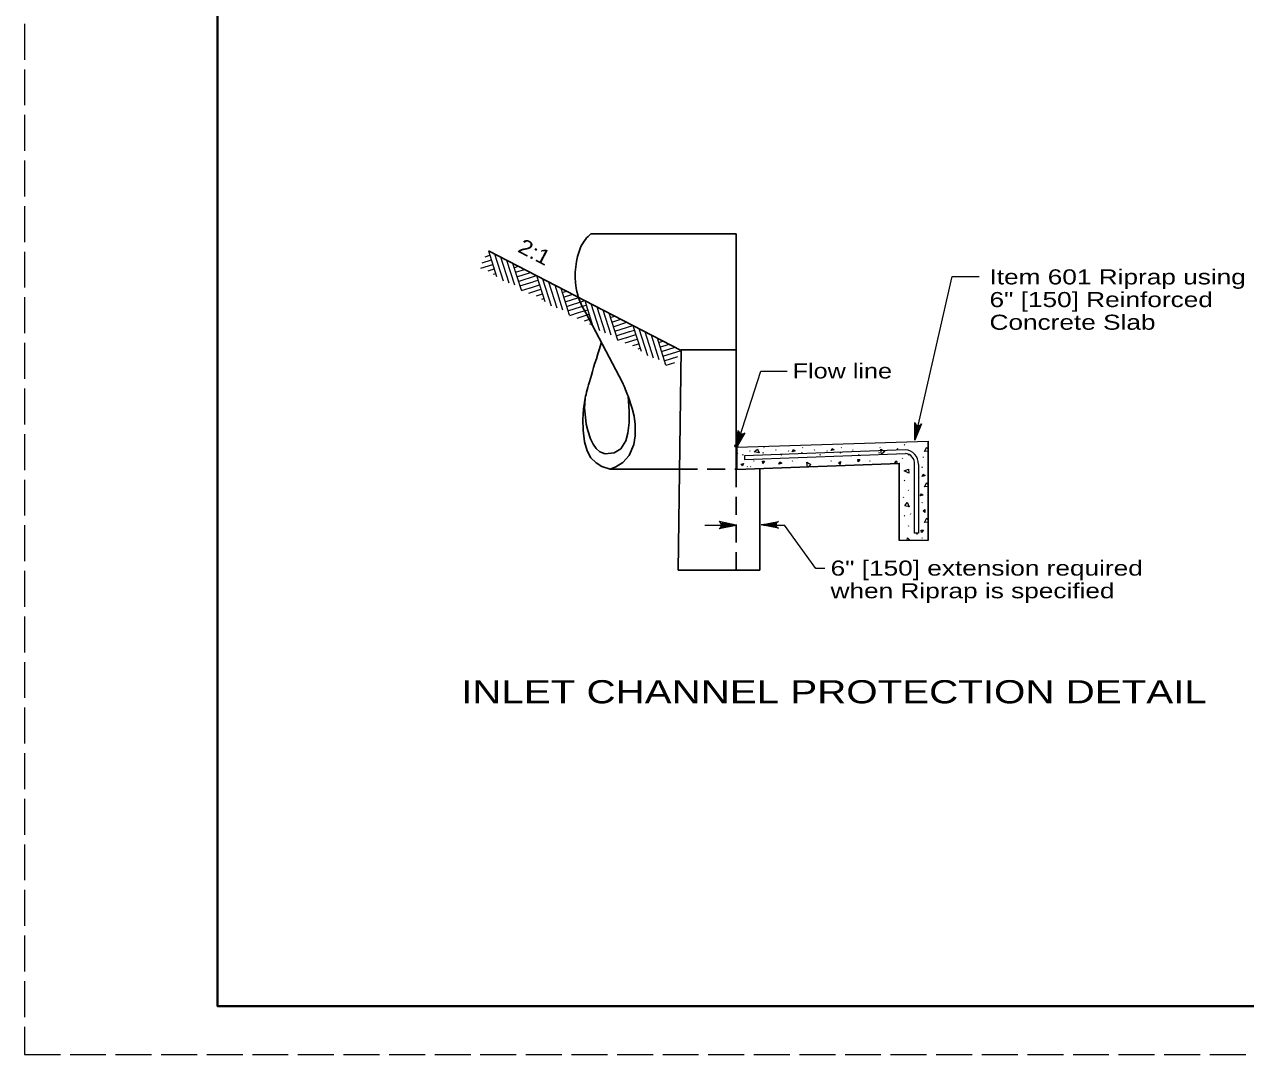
# Model space of a CAD drawing. Extents: x 685.4 to 719.4, y 1059.8 to 1105.8.
# Drawn here: x 685.44 to 698.08, y 1083.77 to 1094.44 of the extents above; entities that cross this region are included whole.
import ezdxf
from ezdxf.enums import TextEntityAlignment as Align

# ---------------------------------------------------------------- set-up
doc = ezdxf.new("R2010")
doc.units = 0
doc.header["$LTSCALE"] = 0.062
doc.header["$PDMODE"] = 32
doc.header["$PDSIZE"] = 0.031
doc.linetypes.add('LONG_DASHED', pattern=[7.5, 6, -1.5])
doc.linetypes.add('MEDIUM_DASHED', pattern=[4.5, 3, -1.5])
doc.layers.add('1', color=7, linetype='Continuous', lineweight=13)

msp = doc.modelspace()

# ---------------------------------------------------------------- linework, layer by layer
at = {"layer": '1', "lineweight": 25}
for p, q in [((691.30642, 1092.26917), (692.80992, 1092.26892)), ((692.31017, 1092.26892), (692.80992, 1092.26892)), ((690.24483, 1092.09333), (692.23983, 1091.06167)), ((691.63242, 1090.72958), (691.25267, 1091.451)), ((692.21025, 1088.78575), (692.24117, 1091.066)), ((692.24117, 1091.066), (692.80992, 1091.066)), ((692.80992, 1089.83158), (692.80992, 1090.05208)), ((694.79625, 1090.12158), (694.79625, 1089.09375)), ((691.50508, 1089.83183), (692.22567, 1089.83175)), ((693.0545, 1088.78575), (693.0545, 1089.83158)), ((692.21025, 1088.78575), (693.0545, 1088.78575))]:
    msp.add_line(p, q, dxfattribs=at)
at = {"layer": '1'}
for p, q in [((690.24483, 1092.09333), (690.32992, 1091.82583)), ((690.30708, 1092.06108), (690.39608, 1091.78167)), ((690.16467, 1091.91158), (690.29, 1091.95142)), ((690.18025, 1091.96858), (690.275, 1091.99867)), ((690.21258, 1092.031), (690.25992, 1092.04608)), ((690.36942, 1092.02883), (690.45542, 1091.75892)), ((690.43192, 1091.9965), (690.51367, 1091.73942)), ((690.49417, 1091.96442), (690.58267, 1091.6865)), ((690.24275, 1091.88433), (690.305, 1091.90417)), ((690.29783, 1091.84983), (690.32, 1091.85683)), ((690.50917, 1091.91708), (690.5565, 1091.93217)), ((690.52425, 1091.86967), (690.619, 1091.89983)), ((690.53933, 1091.8225), (690.68125, 1091.86758)), ((690.55442, 1091.77525), (690.74358, 1091.83533)), ((690.74358, 1091.83533), (690.82867, 1091.56783)), ((690.56942, 1091.72792), (690.70942, 1091.7725)), ((690.58842, 1091.68183), (690.67708, 1091.71)), ((690.66342, 1091.65367), (690.78875, 1091.6935)), ((690.679, 1091.71058), (690.77367, 1091.74075)), ((690.71133, 1091.77308), (690.75858, 1091.78817)), ((690.80592, 1091.80317), (690.89483, 1091.52375)), ((690.86817, 1091.771), (690.95408, 1091.501)), ((690.93067, 1091.73867), (691.01242, 1091.4815)), ((690.993, 1091.70642), (691.08133, 1091.4285)), ((690.74142, 1091.62642), (690.80375, 1091.64625)), ((690.79667, 1091.59192), (690.81883, 1091.599)), ((691.00792, 1091.65917), (691.05525, 1091.67425)), ((691.023, 1091.61183), (691.11767, 1091.64192)), ((691.03808, 1091.5645), (691.17992, 1091.60967)), ((691.05308, 1091.51733), (691.24225, 1091.5775)), ((691.24225, 1091.5775), (691.3275, 1091.31)), ((691.06817, 1091.47), (691.20817, 1091.51458)), ((691.08717, 1091.42383), (691.17592, 1091.45208)), ((691.16217, 1091.39567), (691.2875, 1091.43558)), ((691.17783, 1091.45275), (691.27242, 1091.48283)), ((691.21008, 1091.51517), (691.25733, 1091.53025)), ((691.30467, 1091.54525), (691.3935, 1091.26575)), ((691.36692, 1091.51308), (691.45283, 1091.24308)), ((691.42933, 1091.48075), (691.51125, 1091.22358)), ((691.49167, 1091.4485), (691.58008, 1091.17067)), ((691.24017, 1091.3685), (691.3025, 1091.38833)), ((691.29542, 1091.334), (691.31758, 1091.34108)), ((691.50675, 1091.40125), (691.55392, 1091.41625)), ((691.52183, 1091.35392), (691.61642, 1091.384)), ((691.53683, 1091.30658), (691.67875, 1091.35183)), ((691.55183, 1091.25933), (691.741, 1091.31958)), ((691.741, 1091.31958), (691.82617, 1091.05208)), ((691.56692, 1091.21217), (691.707, 1091.25658)), ((691.58592, 1091.166), (691.67467, 1091.19425)), ((691.66092, 1091.13775), (691.78617, 1091.17767)), ((691.67658, 1091.19483), (691.77117, 1091.225)), ((691.70883, 1091.25725), (691.75608, 1091.27225)), ((691.80333, 1091.28733), (691.89225, 1091.00792)), ((691.86567, 1091.25508), (691.95158, 1090.98517)), ((691.92808, 1091.22283), (692.01, 1090.96567)), ((691.99042, 1091.19058), (692.07883, 1090.91275)), ((691.73892, 1091.11058), (691.80125, 1091.13042)), ((691.79408, 1091.07608), (691.81633, 1091.08317)), ((692.0055, 1091.14333), (692.05275, 1091.15842)), ((692.02058, 1091.096), (692.11517, 1091.12608)), ((692.03558, 1091.04875), (692.1775, 1091.09392)), ((692.05067, 1091.00142), (692.23983, 1091.06167)), ((692.06567, 1090.95425), (692.20567, 1090.99875)), ((692.08458, 1090.90808), (692.17342, 1090.93633)), ((691.6925, 1090.57925), (691.69067, 1090.58125)), ((691.69908, 1090.55908), (691.69192, 1090.56775)), ((691.24142, 1090.45875), (691.23075, 1090.47133)), ((691.24125, 1090.46367), (691.23133, 1090.47542)), ((691.24425, 1090.52658), (691.2405, 1090.53108)), ((692.83858, 1090.21142), (692.80992, 1090.05208)), ((692.84742, 1090.20275), (692.80992, 1090.05208)), ((692.884, 1090.19842), (692.80992, 1090.05208)), ((692.85767, 1090.19758), (692.80992, 1090.05208)), ((692.87225, 1090.19575), (692.80992, 1090.05208)), ((694.715, 1090.28742), (694.65933, 1090.13308)), ((694.67808, 1090.28725), (694.65933, 1090.13308)), ((694.68892, 1090.28342), (694.65933, 1090.13308)), ((694.70358, 1090.28342), (694.65933, 1090.13308)), ((692.81658, 1090.05992), (694.79625, 1090.12158)), ((693.09658, 1090.05658), (693.10008, 1090.05125)), ((693.49642, 1090.05658), (693.49992, 1090.05125)), ((693.89625, 1090.05658), (693.89975, 1090.05125)), ((694.29608, 1090.05658), (694.29958, 1090.05125)), ((694.47875, 1090.03942), (694.48225, 1090.04742)), ((694.55058, 1090.07842), (694.55425, 1090.08642)), ((692.81658, 1090.03358), (692.81992, 1090.02875)), ((692.81658, 1089.98042), (692.81708, 1089.98058)), ((692.81658, 1089.98042), (692.81708, 1089.98058)), ((692.8245, 1089.99808), (692.82692, 1089.9945)), ((692.87958, 1089.97775), (692.88308, 1089.98558)), ((694.56025, 1090.03208), (692.89742, 1089.97025)), ((692.95142, 1090.01658), (692.95492, 1090.02458)), ((692.99042, 1089.92092), (692.99392, 1089.91558)), ((693.08992, 1089.99808), (693.09342, 1090.00608)), ((693.21608, 1090.03408), (693.21975, 1090.02875)), ((693.27925, 1089.97775), (693.28292, 1089.98558)), ((693.35125, 1090.01658), (693.35475, 1090.02458)), ((693.39025, 1089.92092), (693.39375, 1089.91558)), ((693.48975, 1089.99808), (693.49325, 1090.00608)), ((693.61592, 1090.03408), (693.61942, 1090.02875)), ((693.67908, 1089.97775), (693.68275, 1089.98558)), ((693.75108, 1090.01658), (693.75458, 1090.02458)), ((693.79008, 1089.92092), (693.79358, 1089.91558)), ((693.88958, 1089.99808), (693.89308, 1090.00608)), ((694.01575, 1090.03408), (694.01925, 1090.02875)), ((694.07892, 1089.97775), (694.08242, 1089.98558)), ((694.15092, 1090.01658), (694.15442, 1090.02458)), ((694.18992, 1089.92092), (694.19342, 1089.91558)), ((694.28925, 1089.99808), (694.29292, 1090.00608)), ((694.41558, 1090.03408), (694.41908, 1090.02875)), ((694.53258, 1089.94192), (694.53608, 1089.94992)), ((694.58975, 1089.98258), (694.59325, 1089.97725)), ((694.74575, 1089.95925), (694.74675, 1089.95125)), ((694.79625, 1090.01858), (694.75958, 1090.01542)), ((692.92475, 1089.85975), (692.92717, 1089.85617)), ((692.95883, 1089.85842), (692.96125, 1089.85483)), ((694.69725, 1089.88142), (694.69725, 1089.16908)), ((694.73475, 1089.85042), (694.73825, 1089.85842)), ((694.55058, 1089.71108), (694.55425, 1089.71908)), ((694.69592, 1089.75108), (694.69942, 1089.74575)), ((694.53942, 1089.54675), (694.54042, 1089.53875)), ((694.58975, 1089.61525), (694.59325, 1089.60992)), ((694.79625, 1089.65125), (694.75958, 1089.64825)), ((694.73475, 1089.48308), (694.73825, 1089.49108)), ((694.55058, 1089.34375), (694.55425, 1089.35175)), ((694.61558, 1089.36558), (694.61908, 1089.37358)), ((694.69592, 1089.38375), (694.69942, 1089.37842)), ((694.79625, 1089.28392), (694.75958, 1089.28092)), ((692.486, 1089.25267), (692.80992, 1089.25267)), ((692.64783, 1089.22792), (692.80992, 1089.25267)), ((692.64967, 1089.27508), (692.80992, 1089.25267)), ((692.65392, 1089.23833), (692.80992, 1089.25267)), ((692.65517, 1089.264), (692.80992, 1089.25267)), ((692.65675, 1089.25267), (692.80992, 1089.25267)), ((693.22958, 1089.27708), (693.06933, 1089.25475)), ((693.22417, 1089.26592), (693.06933, 1089.25475)), ((693.2225, 1089.25475), (693.06933, 1089.25475)), ((693.22533, 1089.24025), (693.06933, 1089.25475)), ((693.2315, 1089.22992), (693.06933, 1089.25475)), ((693.09333, 1089.25325), (693.30933, 1089.25325)), ((694.58975, 1089.24792), (694.59325, 1089.24275)), ((694.67942, 1089.16292), (694.68025, 1089.15492)), ((694.79625, 1089.09375), (694.49825, 1089.09375)), ((694.73475, 1089.11575), (694.73825, 1089.12375))]:
    msp.add_line(p, q, dxfattribs=at)
at = {"layer": '1', "linetype": 'MEDIUM_DASHED', "lineweight": 25}
for p in [(692.22442, 1089.83167), (692.80992, 1088.78575)]:
    msp.add_line(p, (692.80992, 1089.83158), dxfattribs=at)
at = {"layer": '1', "linetype": 'LONG_DASHED'}
msp.add_lwpolyline([(685.44108, 1083.77067), (719.44108, 1083.77067), (719.44108, 1105.77067), (685.44108, 1105.77067)], close=True, dxfattribs=at)
at = {"layer": '1', "lineweight": 25}
for points in [[(718.94108, 1084.27067), (687.44108, 1084.27067), (687.44108, 1105.27067)], [(692.80992, 1089.83158), (692.80992, 1090.07333), (692.80992, 1092.26892)], [(691.69033, 1090.58583), (691.7315, 1090.46125), (691.75208, 1090.38008), (691.76508, 1090.293), (691.76475, 1090.17633), (691.75142, 1090.08758), (691.70333, 1089.97208), (691.63775, 1089.90017), (691.56467, 1089.85483), (691.50508, 1089.83183), (691.41975, 1089.85808), (691.361, 1089.89658), (691.3065, 1089.94908), (691.26542, 1090.02283), (691.23808, 1090.11575), (691.22458, 1090.23633), (691.22175, 1090.34467), (691.22808, 1090.45533), (691.24625, 1090.56683)], [(691.24625, 1090.56683), (691.24108, 1090.46175), (691.24892, 1090.3685), (691.25833, 1090.29708), (691.27392, 1090.233), (691.30025, 1090.14508), (691.32992, 1090.09192), (691.361, 1090.04617), (691.39842, 1090.00958), (691.45442, 1089.99125), (691.54767, 1090.00033), (691.61483, 1090.04258), (691.66758, 1090.12483), (691.68642, 1090.20367), (691.70192, 1090.31525), (691.7035, 1090.43067), (691.69033, 1090.58583)], [(692.81658, 1090.05992), (692.81658, 1089.82925), (694.49825, 1089.89108), (694.49825, 1089.09375)]]:
    msp.add_lwpolyline(points, dxfattribs=at)
at = {"layer": '1', "lineweight": 40}
msp.add_lwpolyline([(687.44108, 1105.27067), (718.94108, 1105.27067), (718.94108, 1084.27067), (687.44108, 1084.27067)], close=True, dxfattribs=at)
at = {"layer": '1'}
for points in [[(694.66825, 1090.29475), (694.65933, 1090.13308), (695.045, 1091.82717), (695.32558, 1091.82717)], [(692.80992, 1090.05208), (693.06625, 1090.84725), (693.33767, 1090.84725)], [(694.72825, 1090.29992), (694.65933, 1090.13308), (694.65875, 1090.31358)], [(692.89875, 1090.20925), (692.80992, 1090.05208), (692.8315, 1090.23125)], [(693.04642, 1089.99958), (692.99658, 1090.01092), (693.03208, 1090.03975), (693.04625, 1090.00042)], [(694.31442, 1089.98642), (694.30825, 1090.03725), (694.34742, 1090.01392), (694.31525, 1089.98692)], [(694.75875, 1090.01542), (694.78275, 1090.06075), (694.79625, 1090.03042)], [(692.89742, 1089.97025), (692.89742, 1089.93208), (694.56108, 1089.99375)], [(693.54925, 1089.85292), (693.54292, 1089.90375), (693.58225, 1089.88025), (693.55008, 1089.85342)], [(694.59592, 1089.78875), (694.55042, 1089.81275), (694.59225, 1089.83125), (694.59575, 1089.78958)], [(694.69725, 1089.16908), (694.65542, 1089.16908), (694.65542, 1089.87992)], [(694.75875, 1089.64825), (694.78275, 1089.69342), (694.79625, 1089.66308)], [(694.58025, 1089.48825), (694.59958, 1089.44075), (694.55558, 1089.45342), (694.57975, 1089.48758)], [(692.63292, 1089.21733), (692.80992, 1089.25267), (692.63292, 1089.28808)], [(693.24633, 1089.21925), (693.06933, 1089.25475), (693.24633, 1089.29008)], [(694.75875, 1089.28092), (694.78275, 1089.32608), (694.79625, 1089.29592)], [(693.72758, 1088.80308), (693.634, 1088.80308), (693.30933, 1089.25325)], [(694.58108, 1089.09375), (694.58492, 1089.12092), (694.61125, 1089.09375)]]:
    msp.add_lwpolyline(points, dxfattribs=at)
for points in [[(693.79442, 1090.02375), (693.80508, 1090.04592), (693.82292, 1090.03258)], [(693.08575, 1089.88942), (693.08175, 1089.91375), (693.10408, 1089.91308)], [(693.39092, 1090.01192), (693.40158, 1090.03408), (693.41942, 1090.02075)], [(693.88742, 1089.88092), (693.87025, 1089.89858), (693.88892, 1089.91075)], [(694.07308, 1089.90825), (694.06908, 1089.93258), (694.09125, 1089.93192)], [(694.45225, 1089.89608), (694.46292, 1089.91842), (694.48075, 1089.90508)], [(692.88725, 1089.88875), (692.87492, 1089.86758), (692.85825, 1089.88225)], [(693.25292, 1089.88375), (693.26342, 1089.90608), (693.28125, 1089.89275)], [(694.73658, 1089.75725), (694.74708, 1089.77942), (694.76492, 1089.76608)], [(694.71608, 1089.55425), (694.72675, 1089.57642), (694.74442, 1089.56308)], [(694.76242, 1089.38392), (694.74508, 1089.40158), (694.76375, 1089.41375)], [(694.72975, 1089.17675), (694.72575, 1089.20108), (694.74792, 1089.20025)]]:
    msp.add_lwpolyline(points, close=True, dxfattribs=at)
for centre, start, end in [((694.69618, 1090.32084), 190.95335, 326.77948), ((692.86955, 1090.23385), 183.90586, 319.73199), ((692.61865, 1089.25273), 292.08605, 67.91218), ((693.26066, 1089.25468), 112.08782, 247.91395)]:
    msp.add_arc(centre, 0.0382, start, end, dxfattribs=at)
at = {"layer": '1', "lineweight": 25}
for centre, major_axis, start_param, end_param in [((691.50509, 1091.93378), (0, 0.40878), 0.60853498, 1.05234758), ((691.71947, 1091.83582), (0, -0.67756), 4.25283424, 4.90421148), ((691.66454, 1091.82525), (0, -0.61216), 4.9073919, 5.37012799)]:
    msp.add_ellipse(centre, major_axis=major_axis, ratio=0.850089, start_param=start_param, end_param=end_param, dxfattribs=at)
at = {"layer": '1'}
for centre, major_axis, start_param, end_param in [((694.54912, 1089.88417), (0.14828, 0), 6.26425159, 7.7784976), ((694.55525, 1089.89283), (0.10113, 0), 6.15569987, 7.79576288)]:
    msp.add_ellipse(centre, major_axis=major_axis, ratio=0.999895, start_param=start_param, end_param=end_param, dxfattribs=at)
at = {"layer": '1', "lineweight": 25}
for points in [[(691.24625, 1090.56683), (691.26758, 1090.66392), (691.3125, 1090.81958), (691.41375, 1091.13625)], [(691.63242, 1090.72958), (691.65517, 1090.67658), (691.67433, 1090.62883), (691.69033, 1090.58583)]]:
    msp.add_open_spline(points, degree=3, dxfattribs=at)
at = {"layer": '1'}
msp.add_point((692.80992, 1090.07333), dxfattribs=at)

# ---------------------------------------------------------------- texts
at = {"layer": '1', "width": 1.15}
msp.add_text('2:1', height=0.156, rotation=332.655, dxfattribs=at).set_placement((690.53767, 1092.08683))
at = {"layer": '1'}
for s, width, p in [('Item 601 Riprap using', 1.3, (695.43267, 1091.74417)), ('6" [150] Reinforced', 1.3, (695.43267, 1091.5095)), ('Concrete Slab ', 1.3, (695.43267, 1091.27483)), ('Flow line', 1.25, (693.39442, 1090.77075)), ('6" [150] extension required', 1.3, (693.78725, 1088.72925)), ('when Riprap is specified', 1.3, (693.78725, 1088.49458))]:
    msp.add_text(s, height=0.156, dxfattribs=dict(at, width=width)).set_placement(p)
at = {"layer": '1', "width": 1.3}
msp.add_text('INLET CHANNEL PROTECTION DETAIL', height=0.24, dxfattribs=at).set_placement((693.822, 1087.40692), align=Align.CENTER)

doc.saveas('drawing.dxf')
